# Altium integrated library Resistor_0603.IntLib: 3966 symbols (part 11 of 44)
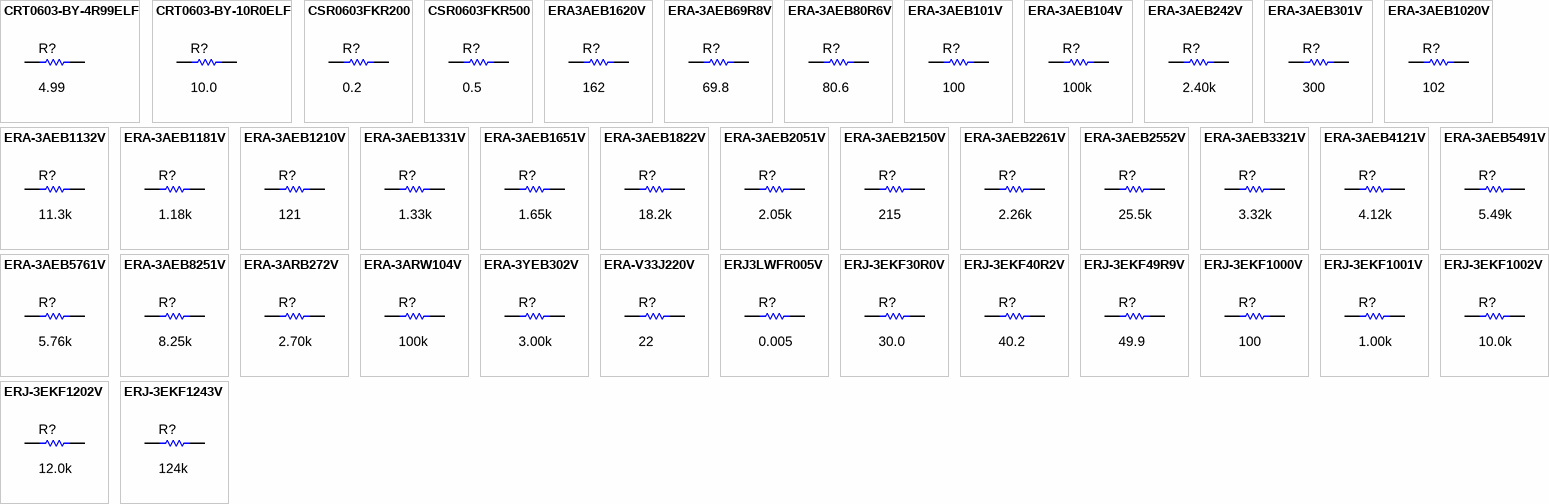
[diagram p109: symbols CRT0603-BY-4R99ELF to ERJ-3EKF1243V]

## ERA-3AEB2150V
designator R?  ValueDisplayed: 215  (hidden comment: ERA-3AEB2150V)
RES, 215, 0.1%, 0.1 W, AEC-Q200 Grade 0, 0603; Manufacturer: Panasonic; CompType: Resistor; Value: 215; Value_Code: 215R; Tolerance_%: 0.1; Value2: 0.1W; VDC_V: 75; TempCo: 25 ppm/C; SizeArea_mm2: 1.28; SizeX_mm: 1.6; SizeY_mm: 0.8; SizeZ_mm: 1; EIA_Code: E192; U/M: EA; AEC Category: Q200; AEC Qualified: Y; AEC Grade: 0
signal-integrity model Resistor
simulation model Resistor
footprint 0603
footprint 0603M
footprint 0603L
footprint 0603_HV
footprint 0603S
pins: 1, 2

## ERA-3AEB2261V
designator R?  ValueDisplayed: 2.26k  (hidden comment: ERA-3AEB2261V)
RES, 2.26 k, 0.1%, 0.1 W, AEC-Q200 Grade 0, 0603; Manufacturer: Panasonic; CompType: Resistor; Value: 2.26k; Res_ohm: 2260; Value_Code: 2k26; Tolerance_%: 0.1; Value2: 0.1W; VDC_V: 75; TempCo: 25 ppm/C; SizeArea_mm2: 1.28; SizeX_mm: 1.6; SizeY_mm: 0.8; SizeZ_mm: 1; EIA_Code: E192; U/M: EA; AEC Category: Q200; AEC Qualified: Y; AEC Grade: 0
signal-integrity model Resistor
simulation model Resistor
footprint 0603
footprint 0603M
footprint 0603L
footprint 0603_HV
footprint 0603S
pins: 1, 2

## ERA-3AEB2552V
designator R?  ValueDisplayed: 25.5k  (hidden comment: ERA-3AEB2552V)
RES, 25.5 k, 0.1%, 0.1 W, AEC-Q200 Grade 0, 0603; Manufacturer: Panasonic; CompType: Resistor; Value: 25.5k; Res_ohm: 25500; Value_Code: 25k5; Tolerance_%: 0.1; Value2: 0.1W; VDC_V: 75; TempCo: 25 ppm/C; SizeArea_mm2: 1.28; SizeX_mm: 1.6; SizeY_mm: 0.8; SizeZ_mm: 1; EIA_Code: E192; U/M: EA; AEC Category: Q200; AEC Qualified: Y; AEC Grade: 0; Green_Lifecycle: Not Set; Green_REACh: Incomplete
signal-integrity model Resistor
simulation model Resistor
footprint 0603
footprint 0603M
footprint 0603L
footprint 0603_HV
footprint 0603S
pins: 1, 2

## ERA-3AEB3321V
designator R?  ValueDisplayed: 3.32k  (hidden comment: ERA-3AEB3321V)
RES, 3.32 k, 0.1%, 0.1 W, AEC-Q200 Grade 0, 0603; Manufacturer: Panasonic; CompType: Resistor; Value: 3.32k; Res_ohm: 3320; Value_Code: 3k32; Tolerance_%: 0.1; Value2: 0.1W; VDC_V: 75; TempCo: 25 ppm/C; SizeArea_mm2: 1.28; SizeX_mm: 1.6; SizeY_mm: 0.8; SizeZ_mm: 1; EIA_Code: E192; U/M: EA; AEC Category: Q200; AEC Qualified: Y; AEC Grade: 0
signal-integrity model Resistor
simulation model Resistor
footprint 0603
footprint 0603M
footprint 0603L
footprint 0603_HV
footprint 0603S
pins: 1, 2

## ERA-3AEB4121V
designator R?  ValueDisplayed: 4.12k  (hidden comment: ERA-3AEB4121V)
RES, 4.12 k, 0.1%, 0.1 W, AEC-Q200 Grade 0, 0603; Manufacturer: Panasonic; CompType: Resistor; Value: 4.12k; Res_ohm: 4120; Value_Code: 4k12; Tolerance_%: 0.1; Value2: 0.1W; VDC_V: 75; TempCo: 25 ppm/C; SizeArea_mm2: 1.28; SizeX_mm: 1.6; SizeY_mm: 0.8; SizeZ_mm: 1; EIA_Code: E192; U/M: EA; AEC Category: Q200; AEC Qualified: Y; AEC Grade: 0
signal-integrity model Resistor
simulation model Resistor
footprint 0603
footprint 0603M
footprint 0603L
footprint 0603_HV
footprint 0603S
pins: 1, 2

## ERA-3AEB5491V
designator R?  ValueDisplayed: 5.49k  (hidden comment: ERA-3AEB5491V)
RES, 5.49 k, 0.1%, 0.1 W, AEC-Q200 Grade 0, 0603; Manufacturer: Panasonic; CompType: Resistor; Value: 5.49k; Res_ohm: 5490; Value_Code: 5k49; Tolerance_%: 0.1; Value2: 0.1W; VDC_V: 75; TempCo: 25 ppm/C; SizeArea_mm2: 1.28; SizeX_mm: 1.6; SizeY_mm: 0.8; SizeZ_mm: 1; EIA_Code: E192; U/M: EA; AEC Category: Q200; AEC Qualified: Y; AEC Grade: 0
signal-integrity model Resistor
simulation model Resistor
footprint 0603
footprint 0603M
footprint 0603L
footprint 0603_HV
footprint 0603S
pins: 1, 2

## ERA-3AEB5761V
designator R?  ValueDisplayed: 5.76k  (hidden comment: ERA-3AEB5761V)
RES, 5.76 k, 0.1%, 0.1 W, AEC-Q200 Grade 0, 0603; Manufacturer: Panasonic; CompType: Resistor; Value: 5.76k; Res_ohm: 5760; Value_Code: 5k76; Tolerance_%: 0.1; Value2: 0.1W; VDC_V: 75; TempCo: 25 ppm/C; SizeArea_mm2: 1.28; SizeX_mm: 1.6; SizeY_mm: 0.8; SizeZ_mm: 1; EIA_Code: E192; U/M: EA; AEC Category: Q200; AEC Qualified: Y; AEC Grade: 0
signal-integrity model Resistor
simulation model Resistor
footprint 0603
footprint 0603M
footprint 0603L
footprint 0603_HV
footprint 0603S
pins: 1, 2

## ERA-3AEB8251V
designator R?  ValueDisplayed: 8.25k  (hidden comment: ERA-3AEB8251V)
RES, 8.25 k, 0.1%, 0.1 W, AEC-Q200 Grade 0, 0603; Manufacturer: Panasonic; CompType: Resistor; Value: 8.25k; Res_ohm: 8250; Value_Code: 8k25; Tolerance_%: 0.1; Value2: 0.1W; VDC_V: 75; TempCo: 25 ppm/C; SizeArea_mm2: 1.28; SizeX_mm: 1.6; SizeY_mm: 0.8; SizeZ_mm: 1; EIA_Code: E192; U/M: EA; AEC Category: Q200; AEC Qualified: Y; AEC Grade: 0
signal-integrity model Resistor
simulation model Resistor
footprint 0603
footprint 0603M
footprint 0603L
footprint 0603_HV
footprint 0603S
pins: 1, 2

## ERA-3ARB272V
designator R?  ValueDisplayed: 2.70k  (hidden comment: ERA-3ARB272V)
RES, 2.70 k, 0.1%, 0.1 W, 0603; Manufacturer: Panasonic; CompType: Resistor; Value: 2.70k; Res_ohm: 2700; Value_Code: 2k70; Tolerance_%: 0.1; Value2: 0.1W; VDC_V: 75; TempCo: 10 ppm/C; SizeArea_mm2: 1.28; SizeX_mm: 1.6; SizeY_mm: 0.8; SizeZ_mm: 1; U/M: EA; AEC Category: Q200
signal-integrity model Resistor
simulation model Resistor
footprint 0603
footprint 0603M
footprint 0603L
footprint 0603_HV
footprint 0603S
pins: 1, 2

## ERA-3ARW104V
designator R?  ValueDisplayed: 100k  (hidden comment: ERA-3ARW104V)
RES, 100 k, 0.05%, 0.1 W, AEC-Q200 Grade 0, 0603; Manufacturer: Panasonic; CompType: Resistor; Value: 100k; Res_ohm: 100000; Tolerance_%: 0.05; Power_W: 0.1; Value2: 0.1W; VDC_V: 75; TempCo: 10 ppm/C; SizeArea_mm2: 1.28; SizeX_mm: 1.6; SizeY_mm: 0.8; SizeZ_mm: 1; U/M: EA; AEC Category: Q200; AEC Qualified: Y; AEC Grade: 0
signal-integrity model Resistor
simulation model Resistor
footprint 0603
footprint 0603M
footprint 0603L
footprint 0603_HV
footprint 0603S
pins: 1, 2

## ERA-3YEB302V
designator R?  ValueDisplayed: 3.00k  (hidden comment: ERA-3YEB302V)
RES, 3.00 k, 0.1%, 0.1 W, 0603; Manufacturer: Panasonic; CompType: Resistor; Value: 3.00k; Res_ohm: 3000; Value_Code: 3k00; Tolerance_%: 0.1; Value2: 0.1W; VDC_V: 75; TempCo: 25 ppm/C; SizeArea_mm2: 1.28; SizeX_mm: 1.6; SizeY_mm: 0.8; SizeZ_mm: 1; U/M: EA; AEC Category: Q200
signal-integrity model Resistor
simulation model Resistor
footprint 0603
footprint 0603M
footprint 0603L
footprint 0603_HV
footprint 0603S
pins: 1, 2

## ERA-V33J220V
designator R?  ValueDisplayed: 22  (hidden comment: ERA-V33J220V)
RES, 22, 5%, 0.063 W, 0603; Manufacturer: Panasonic; CompType: Resistor; Value: 22; Value_Code: 22R0; Tolerance_%: 5; Power_W: 0.063; Value2: 0.063W; TempCo: 3300 ppm/C; SizeArea_mm2: 1.28; SizeX_mm: 1.6; SizeY_mm: 0.8; SizeZ_mm: 1; EIA_Code: E24; U/M: EA; AEC Category: Q200; AEC Qualified: N; Green_Lifecycle: Not Set; Green_REACh: Incomplete
signal-integrity model Resistor
simulation model Resistor
footprint 0603
footprint 0603M
footprint 0603L
footprint 0603_HV
footprint 0603S
pins: 1, 2

## ERJ3LWFR005V
designator R?  ValueDisplayed: 0.005  (hidden comment: ERJ3LWFR005V)
RES, 0.005, 1%, 0.25 W, AEC-Q200 Grade 1, 0603; Manufacturer: Panasonic; CompType: Resistor; Value: 0.005; Value_Code: 5L000; Tolerance_%: 1; Power_W: 0.25; Value2: 0.25W; TempCo: ppm/C; SizeArea_mm2: 1.28; SizeX_mm: 1.6; SizeY_mm: 0.8; EIA_Code: E96; U/M: EA; AEC Category: Q200; AEC Qualified: Y; Green_Lifecycle: Not Set; Green_REACh: Incomplete
signal-integrity model Resistor
simulation model Resistor
footprint 0603
footprint 0603M
footprint 0603L
footprint 0603_HV
footprint 0603S
pins: 1, 2

## ERJ-3EKF30R0V
designator R?  ValueDisplayed: 30.0  (hidden comment: ERJ-3EKF30R0V)
RES, 30.0, 1%, 0.1 W, AEC-Q200 Grade 0, 0603; Manufacturer: Panasonic; CompType: Resistor; Value: 30.0; Res_ohm: 30; Value_Code: 30R0; Tolerance_%: 1; Power_W: 0.1; Value2: 0.1W; TempCo: 100 ppm/C; SizeArea_mm2: 1.28; SizeX_mm: 1.6; SizeY_mm: 0.8; U/M: EA; AEC Category: Q200; AEC Qualified: Y; AEC Grade: 0
signal-integrity model Resistor
simulation model Resistor
footprint 0603
footprint 0603M
footprint 0603L
footprint 0603_HV
footprint 0603S
pins: 1, 2

## ERJ-3EKF40R2V
designator R?  ValueDisplayed: 40.2  (hidden comment: ERJ-3EKF40R2V)
RES, 40.2, 1%, 0.1 W, AEC-Q200 Grade 0, 0603; Manufacturer: Panasonic; CompType: Resistor; Value: 40.2; Value_Code: 40R2; Tolerance_%: 1; Power_W: 0.1; Value2: 0.1W; TempCo: 100 ppm/C; SizeArea_mm2: 1.28; SizeX_mm: 1.6; SizeY_mm: 0.8; EIA_Code: E96; U/M: EA; AEC Category: Q200; AEC Qualified: Y; AEC Grade: 0; Green_Lifecycle: Active; Green_REACh: Passed
signal-integrity model Resistor
simulation model Resistor
footprint 0603
footprint 0603M
footprint 0603L
footprint 0603_HV
footprint 0603S
pins: 1, 2

## ERJ-3EKF49R9V
designator R?  ValueDisplayed: 49.9  (hidden comment: ERJ-3EKF49R9V)
RES, 49.9, 1%, 0.1 W, AEC-Q200 Grade 0, 0603; Manufacturer: Panasonic; CompType: Resistor; Value: 49.9; Value_Code: 49R9; Tolerance_%: 1; Power_W: 0.1; Value2: 0.1W; TempCo: 100 ppm/C; SizeArea_mm2: 1.28; SizeX_mm: 1.6; SizeY_mm: 0.8; EIA_Code: E96; U/M: EA; AEC Category: Q200; AEC Qualified: Y; AEC Grade: 0; Green_Lifecycle: Active; Green_REACh: Passed
signal-integrity model Resistor
simulation model Resistor
footprint 0603
footprint 0603M
footprint 0603L
footprint 0603_HV
footprint 0603S
pins: 1, 2

## ERJ-3EKF1000V
designator R?  ValueDisplayed: 100  (hidden comment: ERJ-3EKF1000V)
RES, 100, 1%, 0.1 W, AEC-Q200 Grade 0, 0603; Manufacturer: Panasonic; CompType: Resistor; Value: 100; Value_Code: 100R; Tolerance_%: 1; Power_W: 0.1; Value2: 0.1W; TempCo: 100 ppm/C; SizeArea_mm2: 1.28; SizeX_mm: 1.6; SizeY_mm: 0.8; EIA_Code: E96; U/M: EA; AEC Category: Q200; AEC Qualified: Y; AEC Grade: 0; Green_Lifecycle: Active; Green_REACh: Passed
signal-integrity model Resistor
simulation model Resistor
footprint 0603
footprint 0603M
footprint 0603L
footprint 0603_HV
footprint 0603S
pins: 1, 2

## ERJ-3EKF1001V
designator R?  ValueDisplayed: 1.00k  (hidden comment: ERJ-3EKF1001V)
RES, 1.00 k, 1%, 0.1 W, AEC-Q200 Grade 0, 0603; Manufacturer: Panasonic; CompType: Resistor; Value: 1.00k; Res_ohm: 1000; Value_Code: 1k00; Tolerance_%: 1; Power_W: 0.1; Value2: 0.1W; VDC_V: 75; TempCo: 100 ppm/C; SizeArea_mm2: 1.28; SizeX_mm: 1.6; SizeY_mm: 0.8; EIA_Code: E96; U/M: EA; AEC Category: Q200; AEC Qualified: Y; AEC Grade: 0; Green_Lifecycle: Active; Green_REACh: Passed
signal-integrity model Resistor
simulation model Resistor
footprint 0603
footprint 0603M
footprint 0603L
footprint 0603_HV
footprint 0603S
pins: 1, 2

## ERJ-3EKF1002V
designator R?  ValueDisplayed: 10.0k  (hidden comment: ERJ-3EKF1002V)
RES, 10.0 k, 1%, 0.1 W, 0603; Manufacturer: Panasonic; CompType: Resistor; Value: 10.0k; Res_ohm: 10000; Value_Code: 10k0; Tolerance_%: 1; Power_W: 0.1; Value2: 0.1W; VDC_V: 75; TempCo: 100 ppm/C; SizeArea_mm2: 1.28; SizeX_mm: 1.6; SizeY_mm: 0.8; EIA_Code: E96; U/M: EA; AEC Category: Q200; Green_Lifecycle: Active; Green_REACh: Passed
signal-integrity model Resistor
simulation model Resistor
footprint 0603
footprint 0603M
footprint 0603L
footprint 0603_HV
footprint 0603S
pins: 1, 2

## ERJ-3EKF1202V
designator R?  ValueDisplayed: 12.0k  (hidden comment: ERJ-3EKF1202V)
RES, 12.0 k, 1%, 0.1 W, 0603; Manufacturer: Panasonic; CompType: Resistor; Value: 12.0k; Res_ohm: 12000; Value_Code: 12k0; Tolerance_%: 1; Power_W: 0.1; Value2: 0.1W; VDC_V: 75; TempCo: 100 ppm/C; SizeArea_mm2: 1.28; SizeX_mm: 1.6; SizeY_mm: 0.8; U/M: EA; AEC Category: Q200; Green_Lifecycle: Active; Green_REACh: Passed
signal-integrity model Resistor
simulation model Resistor
footprint 0603
footprint 0603M
footprint 0603L
footprint 0603_HV
footprint 0603S
pins: 1, 2

## ERJ-3EKF1243V
designator R?  ValueDisplayed: 124k  (hidden comment: ERJ-3EKF1243V)
RES, 124 k, 1%, 0.1 W, AEC-Q200 Grade 0, 0603; Manufacturer: Panasonic; CompType: Resistor; Value: 124k; Res_ohm: 124000; Tolerance_%: 1; Power_W: 0.1; Value2: 0.1W; VDC_V: 75; TempCo: 100 ppm/C; SizeArea_mm2: 1.28; SizeX_mm: 1.6; SizeY_mm: 0.8; EIA_Code: E96; U/M: EA; AEC Category: Q200; AEC Qualified: Y; AEC Grade: 0
signal-integrity model Resistor
simulation model Resistor
footprint 0603
footprint 0603M
footprint 0603L
footprint 0603_HV
footprint 0603S
pins: 1, 2

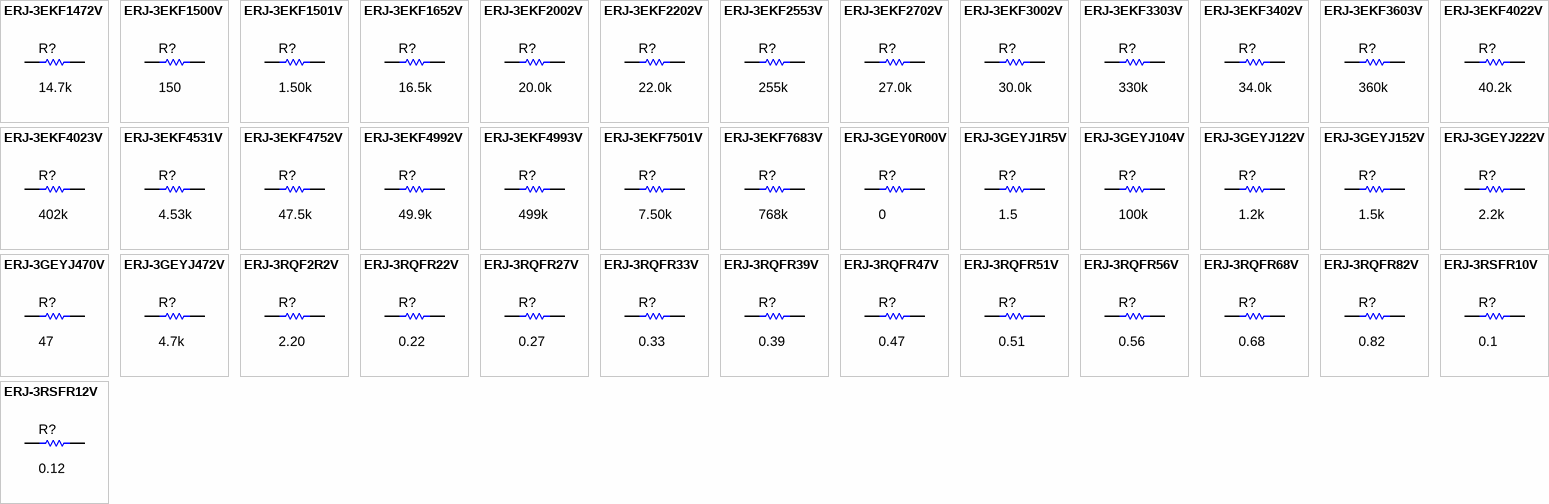
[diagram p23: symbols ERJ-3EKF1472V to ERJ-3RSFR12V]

## ERJ-3EKF1472V
designator R?  ValueDisplayed: 14.7k  (hidden comment: ERJ-3EKF1472V)
RES, 14.7 k, 1%, 0.1 W, AEC-Q200 Grade 0, 0603; Manufacturer: Panasonic; CompType: Resistor; Value: 14.7k; Res_ohm: 14700; Value_Code: 14k7; Tolerance_%: 1; Power_W: 0.1; Value2: 0.1W; VDC_V: 50; TempCo: 100 ppm/C; SizeArea_mm2: 1.28; SizeX_mm: 1.6; SizeY_mm: 0.8; EIA_Code: E96; U/M: EA; AEC Category: Q200; AEC Qualified: Y; AEC Grade: 0; Green_Lifecycle: Active; Green_REACh: Passed
signal-integrity model Resistor
simulation model Resistor
footprint 0603
footprint 0603M
footprint 0603L
footprint 0603_HV
footprint 0603S
pins: 1, 2

## ERJ-3EKF1500V
designator R?  ValueDisplayed: 150  (hidden comment: ERJ-3EKF1500V)
RES, 150, 1%, 0.1 W, AEC-Q200 Grade 0, 0603; Manufacturer: Panasonic; CompType: Resistor; Value: 150; Value_Code: 150R; Tolerance_%: 1; Power_W: 0.1; Value2: 0.1W; VDC_V: 50; TempCo: 100 ppm/C; SizeArea_mm2: 1.28; SizeX_mm: 1.6; SizeY_mm: 0.8; EIA_Code: E96; U/M: EA; AEC Category: Q200; AEC Qualified: Y; AEC Grade: 0; Green_Lifecycle: Active; Green_REACh: Passed
signal-integrity model Resistor
simulation model Resistor
footprint 0603
footprint 0603M
footprint 0603L
footprint 0603_HV
footprint 0603S
pins: 1, 2

## ERJ-3EKF1501V
designator R?  ValueDisplayed: 1.50k  (hidden comment: ERJ-3EKF1501V)
RES, 1.50 k, 1%, 0.1 W, 0603; Manufacturer: Panasonic; CompType: Resistor; Value: 1.50k; Res_ohm: 1500; Value_Code: 1k50; Tolerance_%: 1; Power_W: 0.1; Value2: 0.1W; VDC_V: 75; TempCo: 100 ppm/C; SizeArea_mm2: 1.28; SizeX_mm: 1.6; SizeY_mm: 0.8; EIA_Code: E96; U/M: EA; AEC Category: Q200; Green_Lifecycle: Active; Green_REACh: Passed
signal-integrity model Resistor
simulation model Resistor
footprint 0603
footprint 0603M
footprint 0603L
footprint 0603_HV
footprint 0603S
pins: 1, 2

## ERJ-3EKF1652V
designator R?  ValueDisplayed: 16.5k  (hidden comment: ERJ-3EKF1652V)
RES, 16.5 k, 1%, 0.1 W, AEC-Q200 Grade 0, 0603; Manufacturer: Panasonic; CompType: Resistor; Value: 16.5k; Res_ohm: 16500; Value_Code: 16k5; Tolerance_%: 1; Power_W: 0.1; Value2: 0.1W; VDC_V: 75; TempCo: 100 ppm/C; SizeArea_mm2: 1.28; SizeX_mm: 1.6; SizeY_mm: 0.8; EIA_Code: E96; U/M: EA; AEC Category: Q200; AEC Qualified: Y; AEC Grade: 0; Green_Lifecycle: Active; Green_REACh: Passed
signal-integrity model Resistor
simulation model Resistor
footprint 0603
footprint 0603M
footprint 0603L
footprint 0603_HV
footprint 0603S
pins: 1, 2

## ERJ-3EKF2002V
designator R?  ValueDisplayed: 20.0k  (hidden comment: ERJ-3EKF2002V)
RES, 20.0 k, 1%, 0.1 W, AEC-Q200 Grade 0, 0603; Manufacturer: Panasonic; CompType: Resistor; Value: 20.0k; Res_ohm: 20000; Value_Code: 20k0; Tolerance_%: 1; Power_W: 0.1; Value2: 0.1W; VDC_V: 75; TempCo: 100 ppm/C; SizeArea_mm2: 1.28; SizeX_mm: 1.6; SizeY_mm: 0.8; EIA_Code: E96; U/M: EA; AEC Category: Q200; AEC Qualified: Y; AEC Grade: 0; Green_Lifecycle: Active; Green_REACh: Passed
signal-integrity model Resistor
simulation model Resistor
footprint 0603
footprint 0603M
footprint 0603L
footprint 0603_HV
footprint 0603S
pins: 1, 2

## ERJ-3EKF2202V
designator R?  ValueDisplayed: 22.0k  (hidden comment: ERJ-3EKF2202V)
RES, 22.0 k, 1%, 0.1 W, AEC-Q200 Grade 0, 0603; Manufacturer: Panasonic; CompType: Resistor; Value: 22.0k; Res_ohm: 22000; Value_Code: 22k0; Tolerance_%: 1; Power_W: 0.1; Value2: 0.1W; VDC_V: 50; TempCo: 100 ppm/C; SizeArea_mm2: 1.28; SizeX_mm: 1.6; SizeY_mm: 0.8; U/M: EA; AEC Category: Q200; AEC Qualified: Y; AEC Grade: 0; Green_Lifecycle: Active; Green_REACh: Passed
signal-integrity model Resistor
simulation model Resistor
footprint 0603
footprint 0603M
footprint 0603L
footprint 0603_HV
footprint 0603S
pins: 1, 2

## ERJ-3EKF2553V
designator R?  ValueDisplayed: 255k  (hidden comment: ERJ-3EKF2553V)
RES, 255 k, 1%, 0.1 W, AEC-Q200 Grade 0, 0603; Manufacturer: Panasonic; CompType: Resistor; Value: 255k; Res_ohm: 255000; Tolerance_%: 1; Power_W: 0.1; Value2: 0.1W; VDC_V: 75; TempCo: 100 ppm/C; SizeArea_mm2: 1.28; SizeX_mm: 1.6; SizeY_mm: 0.8; EIA_Code: E96; U/M: EA; AEC Category: Q200; AEC Qualified: Y; AEC Grade: 0
signal-integrity model Resistor
simulation model Resistor
footprint 0603
footprint 0603M
footprint 0603L
footprint 0603_HV
footprint 0603S
pins: 1, 2

## ERJ-3EKF2702V
designator R?  ValueDisplayed: 27.0k  (hidden comment: ERJ-3EKF2702V)
RES, 27.0 k, 1%, 0.1 W, AEC-Q200 Grade 0, 0603; Manufacturer: Panasonic; CompType: Resistor; Value: 27.0k; Res_ohm: 27000; Value_Code: 27k0; Tolerance_%: 1; Power_W: 0.1; Value2: 0.1W; VDC_V: 50; TempCo: 100 ppm/C; SizeArea_mm2: 1.28; SizeX_mm: 1.6; SizeY_mm: 0.8; U/M: EA; AEC Category: Q200; AEC Qualified: Y; AEC Grade: 0
signal-integrity model Resistor
simulation model Resistor
footprint 0603
footprint 0603M
footprint 0603L
footprint 0603_HV
footprint 0603S
pins: 1, 2

## ERJ-3EKF3002V
designator R?  ValueDisplayed: 30.0k  (hidden comment: ERJ-3EKF3002V)
RES, 30.0 k, 1%, 0.1 W, AEC-Q200 Grade 0, 0603; Manufacturer: Panasonic; CompType: Resistor; Value: 30.0k; Res_ohm: 30000; Value_Code: 30k0; Tolerance_%: 1; Power_W: 0.1; Value2: 0.1W; VDC_V: 75; TempCo: 100 ppm/C; SizeArea_mm2: 1.28; SizeX_mm: 1.6; SizeY_mm: 0.8; U/M: EA; AEC Category: Q200; AEC Qualified: Y; AEC Grade: 0
signal-integrity model Resistor
simulation model Resistor
footprint 0603
footprint 0603M
footprint 0603L
footprint 0603_HV
footprint 0603S
pins: 1, 2

## ERJ-3EKF3303V
designator R?  ValueDisplayed: 330k  (hidden comment: ERJ-3EKF3303V)
RES, 330 k, 1%, 0.1 W, AEC-Q200 Grade 0, 0603; Manufacturer: Panasonic; CompType: Resistor; Value: 330k; Res_ohm: 330000; Tolerance_%: 1; Power_W: 0.1; Value2: 0.1W; VDC_V: 75; TempCo: 100 ppm/C; SizeArea_mm2: 1.28; SizeX_mm: 1.6; SizeY_mm: 0.8; U/M: EA; AEC Category: Q200; AEC Qualified: Y; AEC Grade: 0; Green_Lifecycle: Active; Green_REACh: Passed
signal-integrity model Resistor
simulation model Resistor
footprint 0603
footprint 0603M
footprint 0603L
footprint 0603_HV
footprint 0603S
pins: 1, 2

## ERJ-3EKF3402V
designator R?  ValueDisplayed: 34.0k  (hidden comment: ERJ-3EKF3402V)
RES, 34.0 k, 1%, 0.1 W, AEC-Q200 Grade 0, 0603; Manufacturer: Panasonic; CompType: Resistor; Value: 34.0k; Res_ohm: 34000; Value_Code: 34k0; Tolerance_%: 1; Power_W: 0.1; Value2: 0.1W; VDC_V: 75; TempCo: 100 ppm/C; SizeArea_mm2: 1.28; SizeX_mm: 1.6; SizeY_mm: 0.8; EIA_Code: E96; U/M: EA; AEC Category: Q200; AEC Qualified: Y; AEC Grade: 0
signal-integrity model Resistor
simulation model Resistor
footprint 0603
footprint 0603M
footprint 0603L
footprint 0603_HV
footprint 0603S
pins: 1, 2

## ERJ-3EKF3603V
designator R?  ValueDisplayed: 360k  (hidden comment: ERJ-3EKF3603V)
RES, 360 k, 1%, 0.1 W, AEC-Q200 Grade 0, 0603; Manufacturer: Panasonic; CompType: Resistor; Value: 360k; Res_ohm: 360000; Tolerance_%: 1; Power_W: 0.1; Value2: 0.1W; VDC_V: 75; TempCo: 100 ppm/C; SizeArea_mm2: 1.28; SizeX_mm: 1.6; SizeY_mm: 0.8; U/M: EA; AEC Category: Q200; AEC Qualified: Y; AEC Grade: 0; Green_Lifecycle: Active; Green_REACh: Passed
signal-integrity model Resistor
simulation model Resistor
footprint 0603
footprint 0603M
footprint 0603L
footprint 0603_HV
footprint 0603S
pins: 1, 2

## ERJ-3EKF4022V
designator R?  ValueDisplayed: 40.2k  (hidden comment: ERJ-3EKF4022V)
RES, 40.2 k, 1%, 0.1 W, AEC-Q200 Grade 0, 0603; Manufacturer: Panasonic; CompType: Resistor; Value: 40.2k; Res_ohm: 40200; Value_Code: 40k2; Tolerance_%: 1; Power_W: 0.1; Value2: 0.1W; VDC_V: 75; TempCo: 100 ppm/C; SizeArea_mm2: 1.28; SizeX_mm: 1.6; SizeY_mm: 0.8; EIA_Code: E96; U/M: EA; AEC Category: Q200; AEC Qualified: Y; AEC Grade: 0; Green_Lifecycle: Active; Green_REACh: Passed
signal-integrity model Resistor
simulation model Resistor
footprint 0603
footprint 0603M
footprint 0603L
footprint 0603_HV
footprint 0603S
pins: 1, 2

## ERJ-3EKF4023V
designator R?  ValueDisplayed: 402k  (hidden comment: ERJ-3EKF4023V)
RES, 402 k, 1%, 0.1 W, AEC-Q200 Grade 0, 0603; Manufacturer: Panasonic; CompType: Resistor; Value: 402k; Res_ohm: 402000; Tolerance_%: 1; Power_W: 0.1; Value2: 0.1W; VDC_V: 50; TempCo: 100 ppm/C; SizeArea_mm2: 1.28; SizeX_mm: 1.6; SizeY_mm: 0.8; EIA_Code: E96; U/M: EA; AEC Category: Q200; AEC Qualified: Y; AEC Grade: 0; Green_Lifecycle: Active; Green_REACh: Passed
signal-integrity model Resistor
simulation model Resistor
footprint 0603
footprint 0603M
footprint 0603L
footprint 0603_HV
footprint 0603S
pins: 1, 2

## ERJ-3EKF4531V
designator R?  ValueDisplayed: 4.53k  (hidden comment: ERJ-3EKF4531V)
RES, 4.53 k, 1%, 0.1 W, AEC-Q200 Grade 0, 0603; Manufacturer: Panasonic; CompType: Resistor; Value: 4.53k; Res_ohm: 4530; Value_Code: 4k53; Tolerance_%: 1; Power_W: 0.1; Value2: 0.1W; VDC_V: 75; TempCo: 100 ppm/C; SizeArea_mm2: 1.28; SizeX_mm: 1.6; SizeY_mm: 0.8; EIA_Code: E96; U/M: EA; AEC Category: Q200; AEC Qualified: Y; AEC Grade: 0
signal-integrity model Resistor
simulation model Resistor
footprint 0603
footprint 0603M
footprint 0603L
footprint 0603_HV
footprint 0603S
pins: 1, 2

## ERJ-3EKF4752V
designator R?  ValueDisplayed: 47.5k  (hidden comment: ERJ-3EKF4752V)
RES, 47.5 k, 1%, 0.1 W, AEC-Q200 Grade 0, 0603; Manufacturer: Panasonic; CompType: Resistor; Value: 47.5k; Res_ohm: 47500; Value_Code: 47k5; Tolerance_%: 1; Power_W: 0.1; Value2: 0.1W; VDC_V: 50; TempCo: 100 ppm/C; SizeArea_mm2: 1.28; SizeX_mm: 1.6; SizeY_mm: 0.8; EIA_Code: E96; U/M: EA; AEC Category: Q200; AEC Qualified: Y; AEC Grade: 0; Green_Lifecycle: Active; Green_REACh: Passed
signal-integrity model Resistor
simulation model Resistor
footprint 0603
footprint 0603M
footprint 0603L
footprint 0603_HV
footprint 0603S
pins: 1, 2

## ERJ-3EKF4992V
designator R?  ValueDisplayed: 49.9k  (hidden comment: ERJ-3EKF4992V)
RES, 49.9 k, 1%, 0.1 W, AEC-Q200 Grade 0, 0603; Manufacturer: Panasonic; CompType: Resistor; Value: 49.9k; Res_ohm: 49900; Value_Code: 49k9; Tolerance_%: 1; Power_W: 0.1; Value2: 0.1W; VDC_V: 75; TempCo: 100 ppm/C; SizeArea_mm2: 1.28; SizeX_mm: 1.6; SizeY_mm: 0.8; EIA_Code: E96; U/M: EA; AEC Category: Q200; AEC Qualified: Y; AEC Grade: 0; Green_Lifecycle: Active; Green_REACh: Passed
signal-integrity model Resistor
simulation model Resistor
footprint 0603
footprint 0603M
footprint 0603L
footprint 0603_HV
footprint 0603S
pins: 1, 2

## ERJ-3EKF4993V
designator R?  ValueDisplayed: 499k  (hidden comment: ERJ-3EKF4993V)
RES, 499 k, 1%, 0.1 W, AEC-Q200 Grade 0, 0603; Manufacturer: Panasonic; CompType: Resistor; Value: 499k; Res_ohm: 499000; Tolerance_%: 1; Power_W: 0.1; Value2: 0.1W; VDC_V: 75; TempCo: 100 ppm/C; SizeArea_mm2: 1.28; SizeX_mm: 1.6; SizeY_mm: 0.8; EIA_Code: E96; U/M: EA; AEC Category: Q200; AEC Qualified: Y; AEC Grade: 0; Green_Lifecycle: Active; Green_REACh: Passed
signal-integrity model Resistor
simulation model Resistor
footprint 0603
footprint 0603M
footprint 0603L
footprint 0603_HV
footprint 0603S
pins: 1, 2

## ERJ-3EKF7501V
designator R?  ValueDisplayed: 7.50k  (hidden comment: ERJ-3EKF7501V)
RES, 7.50 k, 1%, 0.1 W, 0603; Manufacturer: Panasonic; CompType: Resistor; Value: 7.50k; Res_ohm: 7500; Value_Code: 7k50; Tolerance_%: 1; Power_W: 0.1; Value2: 0.1W; VDC_V: 75; TempCo: 100 ppm/C; SizeArea_mm2: 1.28; SizeX_mm: 1.6; SizeY_mm: 0.8; EIA_Code: E96; U/M: EA; AEC Category: Q200; Green_Lifecycle: Active; Green_REACh: Passed
signal-integrity model Resistor
simulation model Resistor
footprint 0603
footprint 0603M
footprint 0603L
footprint 0603_HV
footprint 0603S
pins: 1, 2

## ERJ-3EKF7683V
designator R?  ValueDisplayed: 768k  (hidden comment: ERJ-3EKF7683V)
RES, 768 k, 1%, 0.1 W, 0603; Manufacturer: Panasonic; CompType: Resistor; Value: 768k; Res_ohm: 768000; Tolerance_%: 1; Power_W: 0.1; Value2: 0.1W; VDC_V: 75; TempCo: 100 ppm/C; SizeArea_mm2: 1.28; SizeX_mm: 1.6; SizeY_mm: 0.8; EIA_Code: E96; U/M: EA; AEC Category: Q200
signal-integrity model Resistor
simulation model Resistor
footprint 0603
footprint 0603M
footprint 0603L
footprint 0603_HV
footprint 0603S
pins: 1, 2

## ERJ-3GEY0R00V
designator R?  ValueDisplayed: 0  (hidden comment: ERJ-3GEY0R00V)
RES, 0, 5%, 0.1 W, 0603; Manufacturer: Panasonic; CompType: Resistor; Value: 0; Value_Code: 0000; Tolerance_%: 5; Power_W: 0.1; Value2: 0.1W; VDC_V: 50; TempCo: 600 ppm/C; SizeArea_mm2: 1.28; SizeX_mm: 1.6; SizeY_mm: 0.8; SizeZ_mm: 1; EIA_Code: E24; U/M: EA; AEC Category: Q200; Green_Lifecycle: Active; Green_REACh: Passed
signal-integrity model Resistor
simulation model Resistor
footprint 0603
footprint 0603M
footprint 0603L
footprint 0603_HV
footprint 0603S
pins: 1, 2

## ERJ-3GEYJ1R5V
designator R?  ValueDisplayed: 1.5  (hidden comment: ERJ-3GEYJ1R5V)
RES, 1.5, 5%, 0.1 W, 0603; Manufacturer: Panasonic; CompType: Resistor; Value: 1.5; Value_Code: 1R50; Tolerance_%: 5; Power_W: 0.1; Value2: 0.1W; VDC_V: 75; TempCo: 600 ppm/C; SizeArea_mm2: 1.28; SizeX_mm: 1.6; SizeY_mm: 0.8; SizeZ_mm: 1; EIA_Code: E24; U/M: EA; AEC Category: Q200
signal-integrity model Resistor
simulation model Resistor
footprint 0603
footprint 0603M
footprint 0603L
footprint 0603_HV
footprint 0603S
pins: 1, 2

## ERJ-3GEYJ104V
designator R?  ValueDisplayed: 100k  (hidden comment: ERJ-3GEYJ104V)
RES, 100 k, 5%, 0.1 W, AEC-Q200 Grade 0, 0603; Manufacturer: Panasonic; CompType: Resistor; Value: 100k; Res_ohm: 100000; Tolerance_%: 5; Power_W: 0.1; Value2: 0.1W; VDC_V: 50; TempCo: 200 ppm/C; SizeArea_mm2: 1.28; SizeX_mm: 1.6; SizeY_mm: 0.8; SizeZ_mm: 1; EIA_Code: E24; U/M: EA; AEC Category: Q200; AEC Qualified: Y; AEC Grade: 0; Green_Lifecycle: Active; Green_REACh: Passed
signal-integrity model Resistor
simulation model Resistor
footprint 0603
footprint 0603M
footprint 0603L
footprint 0603_HV
footprint 0603S
pins: 1, 2

## ERJ-3GEYJ122V
designator R?  ValueDisplayed: 1.2k  (hidden comment: ERJ-3GEYJ122V)
RES, 1.2 k, 5%, 0.1 W, AEC-Q200 Grade 0, 0603; Manufacturer: Panasonic; CompType: Resistor; Value: 1.2k; Res_ohm: 1200; Value_Code: 1k20; Tolerance_%: 5; Power_W: 0.1; Value2: 0.1W; VDC_V: 75; TempCo: 200 ppm/C; SizeArea_mm2: 1.28; SizeX_mm: 1.6; SizeY_mm: 0.8; SizeZ_mm: 1; EIA_Code: E24; U/M: EA; AEC Category: Q200; AEC Qualified: Y; AEC Grade: 0; Green_Lifecycle: Active; Green_REACh: Passed
signal-integrity model Resistor
simulation model Resistor
footprint 0603
footprint 0603M
footprint 0603L
footprint 0603_HV
footprint 0603S
pins: 1, 2

## ERJ-3GEYJ152V
designator R?  ValueDisplayed: 1.5k  (hidden comment: ERJ-3GEYJ152V)
RES, 1.5 k, 5%, 0.1 W, AEC-Q200 Grade 0, 0603; Manufacturer: Panasonic; CompType: Resistor; Value: 1.5k; Res_ohm: 1500; Value_Code: 1k50; Tolerance_%: 5; Power_W: 0.1; Value2: 0.1W; VDC_V: 75; TempCo: 200 ppm/C; SizeArea_mm2: 1.28; SizeX_mm: 1.6; SizeY_mm: 0.8; SizeZ_mm: 1; EIA_Code: E24; U/M: EA; AEC Category: Q200; AEC Qualified: Y; AEC Grade: 0; Green_Lifecycle: Active; Green_REACh: Passed
signal-integrity model Resistor
simulation model Resistor
footprint 0603
footprint 0603M
footprint 0603L
footprint 0603_HV
footprint 0603S
pins: 1, 2

## ERJ-3GEYJ222V
designator R?  ValueDisplayed: 2.2k  (hidden comment: ERJ-3GEYJ222V)
RES, 2.2 k, 5%, 0.1 W, AEC-Q200 Grade 0, 0603; Manufacturer: Panasonic; CompType: Resistor; Value: 2.2k; Res_ohm: 2200; Value_Code: 2k20; Tolerance_%: 5; Power_W: 0.1; Value2: 0.1W; VDC_V: 75; TempCo: 200 ppm/C; SizeArea_mm2: 1.28; SizeX_mm: 1.6; SizeY_mm: 0.8; SizeZ_mm: 1; EIA_Code: E24; U/M: EA; AEC Category: Q200; AEC Qualified: Y; AEC Grade: 0; Green_Lifecycle: Active; Green_REACh: Passed
signal-integrity model Resistor
simulation model Resistor
footprint 0603
footprint 0603M
footprint 0603L
footprint 0603_HV
footprint 0603S
pins: 1, 2

## ERJ-3GEYJ470V
designator R?  ValueDisplayed: 47  (hidden comment: ERJ-3GEYJ470V)
RES, 47, 5%, 0.1 W, AEC-Q200 Grade 0, 0603; Manufacturer: Panasonic; CompType: Resistor; Value: 47; Value_Code: 47R0; Tolerance_%: 5; Power_W: 0.1; Value2: 0.1W; TempCo: 200 ppm/C; SizeArea_mm2: 1.28; SizeX_mm: 1.6; SizeY_mm: 0.8; SizeZ_mm: 1; EIA_Code: E24; U/M: EA; AEC Category: Q200; AEC Qualified: Y; AEC Grade: 0; Green_Lifecycle: Active; Green_REACh: Passed
signal-integrity model Resistor
simulation model Resistor
footprint 0603
footprint 0603M
footprint 0603L
footprint 0603_HV
footprint 0603S
pins: 1, 2

## ERJ-3GEYJ472V
designator R?  ValueDisplayed: 4.7k  (hidden comment: ERJ-3GEYJ472V)
RES, 4.7 k, 5%, 0.1 W, AEC-Q200 Grade 0, 0603; Manufacturer: Panasonic; CompType: Resistor; Value: 4.7k; Res_ohm: 4700; Value_Code: 4k70; Tolerance_%: 5; Power_W: 0.1; Value2: 0.1W; VDC_V: 75; TempCo: 200 ppm/C; SizeArea_mm2: 1.28; SizeX_mm: 1.6; SizeY_mm: 0.8; SizeZ_mm: 1; EIA_Code: E24; U/M: EA; AEC Category: Q200; AEC Qualified: Y; AEC Grade: 0; Green_Lifecycle: Active; Green_REACh: Passed
signal-integrity model Resistor
simulation model Resistor
footprint 0603
footprint 0603M
footprint 0603L
footprint 0603_HV
footprint 0603S
pins: 1, 2

## ERJ-3RQF2R2V
designator R?  ValueDisplayed: 2.20  (hidden comment: ERJ-3RQF2R2V)
RES, 2.20, 1%, 0.1 W, 0603; Manufacturer: Panasonic; CompType: Resistor; Value: 2.20; Res_ohm: 2.2; Value_Code: 2R20; Tolerance_%: 1; Power_W: 0.1; Value2: 0.1W; TempCo: 200 ppm/C; SizeArea_mm2: 1.28; SizeX_mm: 1.6; SizeY_mm: 0.8; U/M: EA; AEC Category: Q200
signal-integrity model Resistor
simulation model Resistor
footprint 0603
footprint 0603M
footprint 0603L
footprint 0603_HV
footprint 0603S
pins: 1, 2

## ERJ-3RQFR22V
designator R?  ValueDisplayed: 0.22  (hidden comment: ERJ-3RQFR22V)
RES, 0.22, 1%, 0.1 W, 0603; Manufacturer: Panasonic; CompType: Resistor; Value: 0.22; Value_Code: R220; Tolerance_%: 1; Power_W: 0.1; Value2: 0.1W; TempCo: 300 ppm/C; SizeArea_mm2: 1.28; SizeX_mm: 1.6; SizeY_mm: 0.8; EIA_Code: E96; U/M: EA; AEC Category: Q200; Green_Lifecycle: Active; Green_REACh: Passed
signal-integrity model Resistor
simulation model Resistor
footprint 0603
footprint 0603M
footprint 0603L
footprint 0603_HV
footprint 0603S
pins: 1, 2

## ERJ-3RQFR27V
designator R?  ValueDisplayed: 0.27  (hidden comment: ERJ-3RQFR27V)
RES, 0.27, 1%, 0.1 W, 0603; Manufacturer: Panasonic; CompType: Resistor; Value: 0.27; Value_Code: R270; Tolerance_%: 1; Power_W: 0.1; Value2: 0.1W; TempCo: 300 ppm/C; SizeArea_mm2: 1.28; SizeX_mm: 1.6; SizeY_mm: 0.8; EIA_Code: E96; U/M: EA; AEC Category: Q200
signal-integrity model Resistor
simulation model Resistor
footprint 0603
footprint 0603M
footprint 0603L
footprint 0603_HV
footprint 0603S
pins: 1, 2

## ERJ-3RQFR33V
designator R?  ValueDisplayed: 0.33  (hidden comment: ERJ-3RQFR33V)
RES, 0.33, 1%, 0.1 W, 0603; Manufacturer: Panasonic; CompType: Resistor; Value: 0.33; Value_Code: R330; Tolerance_%: 1; Power_W: 0.1; Value2: 0.1W; TempCo: 300 ppm/C; SizeArea_mm2: 1.28; SizeX_mm: 1.6; SizeY_mm: 0.8; EIA_Code: E96; U/M: EA; AEC Category: Q200; Green_Lifecycle: Active; Green_REACh: Passed
signal-integrity model Resistor
simulation model Resistor
footprint 0603
footprint 0603M
footprint 0603L
footprint 0603_HV
footprint 0603S
pins: 1, 2

## ERJ-3RQFR39V
designator R?  ValueDisplayed: 0.39  (hidden comment: ERJ-3RQFR39V)
RES, 0.39, 1%, 0.1 W, 0603; Manufacturer: Panasonic; CompType: Resistor; Value: 0.39; Value_Code: R390; Tolerance_%: 1; Power_W: 0.1; Value2: 0.1W; TempCo: 300 ppm/C; SizeArea_mm2: 1.28; SizeX_mm: 1.6; SizeY_mm: 0.8; EIA_Code: E96; U/M: EA; AEC Category: Q200; Green_Lifecycle: Active; Green_REACh: Passed
signal-integrity model Resistor
simulation model Resistor
footprint 0603
footprint 0603M
footprint 0603L
footprint 0603_HV
footprint 0603S
pins: 1, 2

## ERJ-3RQFR47V
designator R?  ValueDisplayed: 0.47  (hidden comment: ERJ-3RQFR47V)
RES, 0.47, 1%, 0.1 W, 0603; Manufacturer: Panasonic; CompType: Resistor; Value: 0.47; Value_Code: R470; Tolerance_%: 1; Power_W: 0.1; Value2: 0.1W; TempCo: 300 ppm/C; SizeArea_mm2: 1.28; SizeX_mm: 1.6; SizeY_mm: 0.8; EIA_Code: E96; U/M: EA; AEC Category: Q200; Green_Lifecycle: Active; Green_REACh: Passed
signal-integrity model Resistor
simulation model Resistor
footprint 0603
footprint 0603M
footprint 0603L
footprint 0603_HV
footprint 0603S
pins: 1, 2

## ERJ-3RQFR51V
designator R?  ValueDisplayed: 0.51  (hidden comment: ERJ-3RQFR51V)
RES, 0.51, 1%, 0.1 W, AEC-Q200 Grade 1, 0603; Manufacturer: Panasonic; CompType: Resistor; Value: 0.51; Value_Code: R510; Tolerance_%: 1; Power_W: 0.1; Value2: 0.1W; TempCo: 300 ppm/C; SizeArea_mm2: 1.28; SizeX_mm: 1.6; SizeY_mm: 0.8; EIA_Code: E96; U/M: EA; AEC Category: Q200; AEC Qualified: Y; Green_Lifecycle: Active; Green_REACh: Passed
signal-integrity model Resistor
simulation model Resistor
footprint 0603
footprint 0603M
footprint 0603L
footprint 0603_HV
footprint 0603S
pins: 1, 2

## ERJ-3RQFR56V
designator R?  ValueDisplayed: 0.56  (hidden comment: ERJ-3RQFR56V)
RES, 0.56, 1%, 0.1 W, 0603; Manufacturer: Panasonic; CompType: Resistor; Value: 0.56; Value_Code: R560; Tolerance_%: 1; Power_W: 0.1; Value2: 0.1W; TempCo: 300 ppm/C; SizeArea_mm2: 1.28; SizeX_mm: 1.6; SizeY_mm: 0.8; EIA_Code: E96; U/M: EA; AEC Category: Q200; Green_Lifecycle: Active; Green_REACh: Passed
signal-integrity model Resistor
simulation model Resistor
footprint 0603
footprint 0603M
footprint 0603L
footprint 0603_HV
footprint 0603S
pins: 1, 2

## ERJ-3RQFR68V
designator R?  ValueDisplayed: 0.68  (hidden comment: ERJ-3RQFR68V)
RES, 0.68, 1%, 0.1 W, 0603; Manufacturer: Panasonic; CompType: Resistor; Value: 0.68; Value_Code: R680; Tolerance_%: 1; Power_W: 0.1; Value2: 0.1W; TempCo: 300 ppm/C; SizeArea_mm2: 1.28; SizeX_mm: 1.6; SizeY_mm: 0.8; EIA_Code: E96; U/M: EA; AEC Category: Q200
signal-integrity model Resistor
simulation model Resistor
footprint 0603
footprint 0603M
footprint 0603L
footprint 0603_HV
footprint 0603S
pins: 1, 2

## ERJ-3RQFR82V
designator R?  ValueDisplayed: 0.82  (hidden comment: ERJ-3RQFR82V)
RES, 0.82, 1%, 0.1 W, 0603; Manufacturer: Panasonic; CompType: Resistor; Value: 0.82; Value_Code: R820; Tolerance_%: 1; Power_W: 0.1; Value2: 0.1W; TempCo: 300 ppm/C; SizeArea_mm2: 1.28; SizeX_mm: 1.6; SizeY_mm: 0.8; EIA_Code: E96; U/M: EA; AEC Category: Q200
signal-integrity model Resistor
simulation model Resistor
footprint 0603
footprint 0603M
footprint 0603L
footprint 0603_HV
footprint 0603S
pins: 1, 2

## ERJ-3RSFR10V
designator R?  ValueDisplayed: 0.1  (hidden comment: ERJ-3RSFR10V)
RES, 0.1, 1%, 0.1 W, 0603; Manufacturer: Panasonic; CompType: Resistor; Value: 0.1; Value_Code: R100; Tolerance_%: 1; Value2: 0.1W; TempCo: 300 ppm/C; SizeArea_mm2: 1.28; SizeX_mm: 1.6; SizeY_mm: 0.8; EIA_Code: E96; U/M: EA; AEC Category: Q200; Green_Lifecycle: Not Set; Green_REACh: Incomplete
signal-integrity model Resistor
simulation model Resistor
footprint 0603
footprint 0603M
footprint 0603L
footprint 0603_HV
footprint 0603S
pins: 1, 2

## ERJ-3RSFR12V
designator R?  ValueDisplayed: 0.12  (hidden comment: ERJ-3RSFR12V)
RES, 0.12, 1%, 0.1 W, 0603; Manufacturer: Panasonic; CompType: Resistor; Value: 0.12; Value_Code: R120; Tolerance_%: 1; Power_W: 0.1; Value2: 0.1W; TempCo: 300 ppm/C; SizeArea_mm2: 1.28; SizeX_mm: 1.6; SizeY_mm: 0.8; EIA_Code: E96; U/M: EA; AEC Category: Q200
signal-integrity model Resistor
simulation model Resistor
footprint 0603
footprint 0603M
footprint 0603L
footprint 0603_HV
footprint 0603S
pins: 1, 2

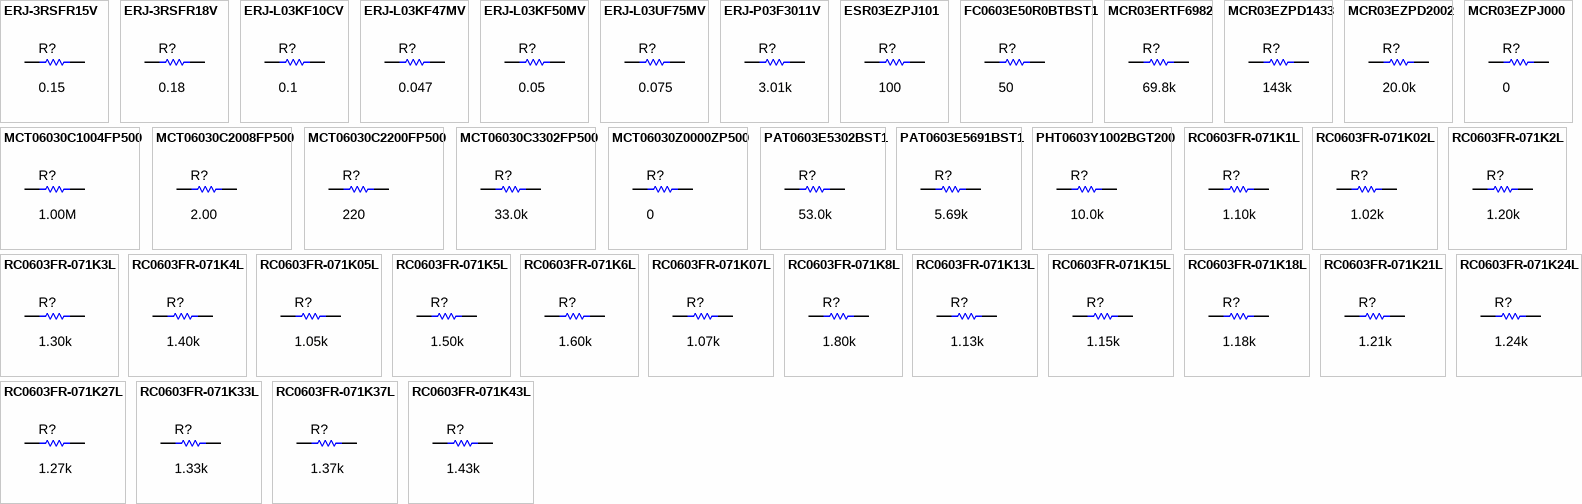
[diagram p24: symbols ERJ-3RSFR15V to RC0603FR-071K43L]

## ERJ-3RSFR15V
designator R?  ValueDisplayed: 0.15  (hidden comment: ERJ-3RSFR15V)
RES, 0.15, 1%, 0.1 W, 0603; Manufacturer: Panasonic; CompType: Resistor; Value: 0.15; Value_Code: R150; Tolerance_%: 1; Power_W: 0.1; Value2: 0.1W; TempCo: 300 ppm/C; SizeArea_mm2: 1.28; SizeX_mm: 1.6; SizeY_mm: 0.8; EIA_Code: E96; U/M: EA; AEC Category: Q200
signal-integrity model Resistor
simulation model Resistor
footprint 0603
footprint 0603M
footprint 0603L
footprint 0603_HV
footprint 0603S
pins: 1, 2

## ERJ-3RSFR18V
designator R?  ValueDisplayed: 0.18  (hidden comment: ERJ-3RSFR18V)
RES, 0.18, 1%, 0.1 W, 0603; Manufacturer: Panasonic; CompType: Resistor; Value: 0.18; Value_Code: R180; Tolerance_%: 1; Power_W: 0.1; Value2: 0.1W; TempCo: 300 ppm/C; SizeArea_mm2: 1.28; SizeX_mm: 1.6; SizeY_mm: 0.8; EIA_Code: E96; U/M: EA; AEC Category: Q200; Green_Lifecycle: Not Set; Green_REACh: Incomplete
signal-integrity model Resistor
simulation model Resistor
footprint 0603
footprint 0603M
footprint 0603L
footprint 0603_HV
footprint 0603S
pins: 1, 2

## ERJ-L03KF10CV
designator R?  ValueDisplayed: 0.1  (hidden comment: ERJ-L03KF10CV)
RES, 0.1, 1%, 0.1 W, 0603; Manufacturer: Panasonic; CompType: Resistor; Value: 0.1; Value_Code: R100; Tolerance_%: 1; Value2: 0.1W; TempCo: 200 ppm/C; SizeArea_mm2: 1.28; SizeX_mm: 1.6; SizeY_mm: 0.8; EIA_Code: E96; U/M: EA; AEC Category: Q200; Green_Lifecycle: Active; Green_REACh: Passed
signal-integrity model Resistor
simulation model Resistor
footprint 0603
footprint 0603M
footprint 0603L
footprint 0603_HV
footprint 0603S
pins: 1, 2

## ERJ-L03KF47MV
designator R?  ValueDisplayed: 0.047  (hidden comment: ERJ-L03KF47MV)
RES, 0.047, 1%, 0.1 W, 0603; Manufacturer: Panasonic; CompType: Resistor; Value: 0.047; Value_Code: R047; Tolerance_%: 1; Power_W: 0.1; Value2: 0.1W; TempCo: 200 ppm/C; SizeArea_mm2: 1.28; SizeX_mm: 1.6; SizeY_mm: 0.8; EIA_Code: E96; U/M: EA; AEC Category: Q200; Green_Lifecycle: Not Set; Green_REACh: Incomplete
signal-integrity model Resistor
simulation model Resistor
footprint 0603
footprint 0603M
footprint 0603L
footprint 0603_HV
footprint 0603S
pins: 1, 2

## ERJ-L03KF50MV
designator R?  ValueDisplayed: 0.05  (hidden comment: ERJ-L03KF50MV)
RES, 0.05, 1%, 0.1 W, 0603; Manufacturer: Panasonic; CompType: Resistor; Value: 0.05; Value_Code: R050; Tolerance_%: 1; Power_W: 0.1; Value2: 0.1W; TempCo: 200 ppm/C; SizeArea_mm2: 1.28; SizeX_mm: 1.6; SizeY_mm: 0.8; EIA_Code: E96; U/M: EA; AEC Category: Q200; Green_Lifecycle: Not Set; Green_REACh: Incomplete
signal-integrity model Resistor
simulation model Resistor
footprint 0603
footprint 0603M
footprint 0603L
footprint 0603_HV
footprint 0603S
pins: 1, 2

## ERJ-L03UF75MV
designator R?  ValueDisplayed: 0.075  (hidden comment: ERJ-L03UF75MV)
RES, 0.075, 1%, 0.1 W, 0603; Manufacturer: Panasonic; CompType: Resistor; Value: 0.075; Value_Code: R075; Tolerance_%: 1; Power_W: 0.1; Value2: 0.1W; TempCo: 200 ppm/C; SizeArea_mm2: 1.28; SizeX_mm: 1.6; SizeY_mm: 0.8; EIA_Code: E96; U/M: EA; AEC Category: Q200
signal-integrity model Resistor
simulation model Resistor
footprint 0603
footprint 0603M
footprint 0603L
footprint 0603_HV
footprint 0603S
pins: 1, 2

## ERJ-P03F3011V
designator R?  ValueDisplayed: 3.01k  (hidden comment: ERJ-P03F3011V)
RES, 3.01 k, 1%, 0.2 W, 0603; Manufacturer: Panasonic; CompType: Resistor; Value: 3.01k; Res_ohm: 3010; Value_Code: 3k01; Tolerance_%: 1; Power_W: 0.2; Value2: 0.2W; VDC_V: 150; TempCo: 200 ppm/C; SizeArea_mm2: 1.28; SizeX_mm: 1.6; SizeY_mm: 0.8; EIA_Code: E96; U/M: EA; AEC Category: Q200
signal-integrity model Resistor
simulation model Resistor
footprint 0603
footprint 0603M
footprint 0603L
footprint 0603_HV
footprint 0603S
pins: 1, 2

## ESR03EZPJ101
designator R?  ValueDisplayed: 100  (hidden comment: ESR03EZPJ101)
RES, 100, 5%, 0.25 W, AEC-Q200 Grade 0, 0603; Manufacturer: Rohm; CompType: Resistor; Value: 100; Value_Code: 100R; Tolerance_%: 5; Power_W: 0.25; Value2: 0.25W; VDC_V: 150; TempCo: 200 ppm/C; SizeArea_mm2: 1.28; SizeX_mm: 1.6; SizeY_mm: 0.8; SizeZ_mm: 1; EIA_Code: E24; U/M: EA; AEC Category: Q200; AEC Qualified: Y; AEC Grade: 0
signal-integrity model Resistor
simulation model Resistor
footprint 0603
footprint 0603M
footprint 0603L
footprint 0603_HV
footprint 0603S
pins: 1, 2

## FC0603E50R0BTBST1
designator R?  ValueDisplayed: 50  (hidden comment: FC0603E50R0BTBST1)
RES, 50, 0.1%, 0.125 W, 0603; Manufacturer: Vishay Thin Film; CompType: Resistor; Value: 50; Value_Code: 50R0; Tolerance_%: 0.1; Power_W: 0.125; Value2: 0.125W; TempCo: 25 ppm/C; SizeArea_mm2: 1.28; SizeX_mm: 1.6; SizeY_mm: 0.8; SizeZ_mm: 1; U/M: EA; AEC Category: Q200; AEC Qualified: N
signal-integrity model Resistor
simulation model Resistor
footprint 0603
footprint 0603M
footprint 0603L
footprint 0603_HV
footprint 0603S
pins: 1, 2

## MCR03ERTF6982
designator R?  ValueDisplayed: 69.8k  (hidden comment: MCR03ERTF6982)
RES, 69.8 k, 1%, 0.1 W, 0603; Manufacturer: Rohm; CompType: Resistor; Value: 69.8k; Res_ohm: 69800; Value_Code: 69k8; Tolerance_%: 1; Power_W: 0.1; Value2: 0.1W; VDC_V: 50; TempCo: 100 ppm/C; SizeArea_mm2: 1.28; SizeX_mm: 1.6; SizeY_mm: 0.8; EIA_Code: E96; U/M: EA; AEC Category: Q200; AEC Qualified: N
signal-integrity model Resistor
simulation model Resistor
footprint 0603
footprint 0603M
footprint 0603L
footprint 0603_HV
footprint 0603S
pins: 1, 2

## MCR03EZPD1433
designator R?  ValueDisplayed: 143k  (hidden comment: MCR03EZPD1433)
RES, 143 k, 0.5%, 0.1 W, 0603; Manufacturer: Rohm; CompType: Resistor; Value: 143k; Res_ohm: 143000; Tolerance_%: 0.5; Power_W: 0.1; Value2: 0.1W; VDC_V: 50; TempCo: 50 ppm/C; SizeArea_mm2: 1.28; SizeX_mm: 1.6; SizeY_mm: 0.8; SizeZ_mm: 1; EIA_Code: E192; U/M: EA; AEC Category: Q200; AEC Qualified: N
signal-integrity model Resistor
simulation model Resistor
footprint 0603
footprint 0603M
footprint 0603L
footprint 0603_HV
footprint 0603S
pins: 1, 2

## MCR03EZPD2002
designator R?  ValueDisplayed: 20.0k  (hidden comment: MCR03EZPD2002)
RES, 20.0 k, 0.5%, 0.1 W, 0603; Manufacturer: Rohm; CompType: Resistor; Value: 20.0k; Res_ohm: 20000; Value_Code: 20k0; Tolerance_%: 0.5; Power_W: 0.1; Value2: 0.1W; VDC_V: 50; TempCo: 50 ppm/C; SizeArea_mm2: 1.28; SizeX_mm: 1.6; SizeY_mm: 0.8; SizeZ_mm: 1; EIA_Code: E192; U/M: EA; AEC Category: Q200; AEC Qualified: N
signal-integrity model Resistor
simulation model Resistor
footprint 0603
footprint 0603M
footprint 0603L
footprint 0603_HV
footprint 0603S
pins: 1, 2

## MCR03EZPJ000
designator R?  ValueDisplayed: 0  (hidden comment: MCR03EZPJ000)
RES, 0, 5%, 0.1 W, 0603; Manufacturer: Rohm; CompType: Resistor; Value: 0; Value_Code: 0000; Tolerance_%: 5; Power_W: 0.1; Value2: 0.1W; VDC_V: 50; TempCo: 400 ppm/C; SizeArea_mm2: 1.28; SizeX_mm: 1.6; SizeY_mm: 0.8; SizeZ_mm: 1; EIA_Code: E24; U/M: EA; AEC Category: Q200; AEC Qualified: N; Green_Lifecycle: Active; Green_REACh: Passed
signal-integrity model Resistor
simulation model Resistor
footprint 0603
footprint 0603M
footprint 0603L
footprint 0603_HV
footprint 0603S
pins: 1, 2

## MCT06030C1004FP500
designator R?  ValueDisplayed: 1.00M  (hidden comment: MCT06030C1004FP500)
RES, 1.00 M, 1%, 0.125 W, 0603; Manufacturer: Vishay/Beyschlag; CompType: Resistor; Value: 1.00Meg; Res_ohm: 1000000; Value_Code: 1M00; Tolerance_%: 1; Power_W: 0.125; Value2: 0.125W; VDC_V: 75; TempCo: 50 ppm/C; SizeArea_mm2: 1.28; SizeX_mm: 1.6; SizeY_mm: 0.8; EIA_Code: E96; U/M: EA; AEC Category: Q200; AEC Qualified: N; Green_Lifecycle: Active; Green_REACh: Passed
signal-integrity model Resistor
simulation model Resistor
footprint 0603
footprint 0603M
footprint 0603L
footprint 0603_HV
footprint 0603S
pins: 1, 2

## MCT06030C2008FP500
designator R?  ValueDisplayed: 2.00  (hidden comment: MCT06030C2008FP500)
RES, 2.00, 1%, 0.125 W, 0603; Manufacturer: Vishay/Beyschlag; CompType: Resistor; Value: 2.00; Res_ohm: 2; Value_Code: 2R00; Tolerance_%: 1; Power_W: 0.125; Value2: 0.125W; TempCo: 50 ppm/C; SizeArea_mm2: 1.28; SizeX_mm: 1.6; SizeY_mm: 0.8; EIA_Code: E96; U/M: EA; AEC Category: Q200; AEC Qualified: N
signal-integrity model Resistor
simulation model Resistor
footprint 0603
footprint 0603M
footprint 0603L
footprint 0603_HV
footprint 0603S
pins: 1, 2

## MCT06030C2200FP500
designator R?  ValueDisplayed: 220  (hidden comment: MCT06030C2200FP500)
RES, 220, 1%, 0.125 W, 0603; Manufacturer: Vishay/Beyschlag; CompType: Resistor; Value: 220; Value_Code: 220R; Tolerance_%: 1; Power_W: 0.125; Value2: 0.125W; VDC_V: 75; TempCo: 50 ppm/C; SizeArea_mm2: 1.28; SizeX_mm: 1.6; SizeY_mm: 0.8; U/M: EA; AEC Category: Q200; AEC Qualified: N
signal-integrity model Resistor
simulation model Resistor
footprint 0603
footprint 0603M
footprint 0603L
footprint 0603_HV
footprint 0603S
pins: 1, 2

## MCT06030C3302FP500
designator R?  ValueDisplayed: 33.0k  (hidden comment: MCT06030C3302FP500)
RES, 33.0 k, 1%, 0.125 W, 0603; Manufacturer: Vishay/Beyschlag; CompType: Resistor; Value: 33.0k; Res_ohm: 33000; Value_Code: 33k0; Tolerance_%: 1; Power_W: 0.125; Value2: 0.125W; VDC_V: 75; TempCo: 50 ppm/C; SizeArea_mm2: 1.28; SizeX_mm: 1.6; SizeY_mm: 0.8; U/M: EA; AEC Category: Q200; AEC Qualified: N
signal-integrity model Resistor
simulation model Resistor
footprint 0603
footprint 0603M
footprint 0603L
footprint 0603_HV
footprint 0603S
pins: 1, 2

## MCT06030Z0000ZP500
designator R?  ValueDisplayed: 0  (hidden comment: MCT06030Z0000ZP500)
RES, 0, 5%, 0.125 W, 0603; Manufacturer: Vishay/Beyschlag; CompType: Resistor; Value: 0; Value_Code: 0000; Tolerance_%: 5; Power_W: 0.125; Value2: 0.125W; TempCo: ppm/C; SizeArea_mm2: 1.28; SizeX_mm: 1.6; SizeY_mm: 0.8; SizeZ_mm: 1; EIA_Code: E24; U/M: EA; AEC Category: Q200; AEC Qualified: N; Green_Lifecycle: Active; Green_REACh: Passed
signal-integrity model Resistor
simulation model Resistor
footprint 0603
footprint 0603M
footprint 0603L
footprint 0603_HV
footprint 0603S
pins: 1, 2

## PAT0603E5302BST1
designator R?  ValueDisplayed: 53.0k  (hidden comment: PAT0603E5302BST1)
RES, 53.0 k, 0.1%, 0.15 W, AEC-Q200 Grade 0, 0603; Manufacturer: Vishay-Dale; CompType: Resistor; Value: 53.0k; Res_ohm: 53000; Value_Code: 53k0; Tolerance_%: 0.1; Power_W: 0.15; Value2: 0.15W; VDC_V: 75; TempCo: 25 ppm/C; SizeArea_mm2: 1.28; SizeX_mm: 1.6; SizeY_mm: 0.8; SizeZ_mm: 1; EIA_Code: E192; U/M: EA; AEC Category: Q200; AEC Qualified: Y; AEC Grade: 0
signal-integrity model Resistor
simulation model Resistor
footprint 0603
footprint 0603M
footprint 0603L
footprint 0603_HV
footprint 0603S
pins: 1, 2

## PAT0603E5691BST1
designator R?  ValueDisplayed: 5.69k  (hidden comment: PAT0603E5691BST1)
RES, 5.69 k, 0.1%, 0.15 W, 0603; Manufacturer: Vishay-Dale; CompType: Resistor; Value: 5.69k; Res_ohm: 5690; Value_Code: 5k69; Tolerance_%: 0.1; Power_W: 0.15; Value2: 0.15W; VDC_V: 75; TempCo: 25 ppm/C; SizeArea_mm2: 1.28; SizeX_mm: 1.6; SizeY_mm: 0.8; SizeZ_mm: 1; EIA_Code: E192; U/M: EA; AEC Category: Q200
signal-integrity model Resistor
simulation model Resistor
footprint 0603
footprint 0603M
footprint 0603L
footprint 0603_HV
footprint 0603S
pins: 1, 2

## PHT0603Y1002BGT200
designator R?  ValueDisplayed: 10.0k  (hidden comment: PHT0603Y1002BGT200)
RES, 10.0 k, 0.1%, 0.0375 W, 0603; Manufacturer: Vishay Sfernice; CompType: Resistor; Value: 10.0k; Res_ohm: 10000; Value_Code: 10k0; Tolerance_%: 0.1; Power_W: 0.0375; VDC_V: 75; TempCo: 15 ppm/C; SizeArea_mm2: 1.28; SizeX_mm: 1.6; SizeY_mm: 0.8; SizeZ_mm: 1; EIA_Code: E192; U/M: EA; AEC Category: Q200
signal-integrity model Resistor
simulation model Resistor
footprint 0603
footprint 0603M
footprint 0603L
footprint 0603_HV
footprint 0603S
pins: 1, 2

## RC0603FR-071K1L
designator R?  ValueDisplayed: 1.10k  (hidden comment: RC0603FR-071K1L)
RES, 1.10 k, 1%, 0.1 W, 0603; Manufacturer: Yageo America; CompType: Resistor; Value: 1.10k; Res_ohm: 1100; Value_Code: 1k10; Tolerance_%: 1; Power_W: 0.1; Value2: 0.1W; VDC_V: 150; TempCo: 200 ppm/C; SizeArea_mm2: 1.28; SizeX_mm: 1.6; SizeY_mm: 0.8; EIA_Code: E96; U/M: EA; AEC Category: Q200; Green_Lifecycle: Active; Green_REACh: Passed
signal-integrity model Resistor
simulation model Resistor
footprint 0603
footprint 0603M
footprint 0603L
footprint 0603_HV
footprint 0603S
pins: 1, 2

## RC0603FR-071K02L
designator R?  ValueDisplayed: 1.02k  (hidden comment: RC0603FR-071K02L)
RES, 1.02 k, 1%, 0.1 W, 0603; Manufacturer: Yageo America; CompType: Resistor; Value: 1.02k; Res_ohm: 1020; Value_Code: 1k02; Tolerance_%: 1; Power_W: 0.1; Value2: 0.1W; VDC_V: 150; TempCo: 200 ppm/C; SizeArea_mm2: 1.28; SizeX_mm: 1.6; SizeY_mm: 0.8; EIA_Code: E96; U/M: EA; AEC Category: Q200
signal-integrity model Resistor
simulation model Resistor
footprint 0603
footprint 0603M
footprint 0603L
footprint 0603_HV
footprint 0603S
pins: 1, 2

## RC0603FR-071K2L
designator R?  ValueDisplayed: 1.20k  (hidden comment: RC0603FR-071K2L)
RES, 1.20 k, 1%, 0.1 W, 0603; Manufacturer: Yageo America; CompType: Resistor; Value: 1.20k; Res_ohm: 1200; Value_Code: 1k20; Tolerance_%: 1; Power_W: 0.1; Value2: 0.1W; VDC_V: 150; TempCo: 200 ppm/C; SizeArea_mm2: 1.28; SizeX_mm: 1.6; SizeY_mm: 0.8; U/M: EA; AEC Category: Q200; Green_Lifecycle: Active; Green_REACh: Passed
signal-integrity model Resistor
simulation model Resistor
footprint 0603
footprint 0603M
footprint 0603L
footprint 0603_HV
footprint 0603S
pins: 1, 2

## RC0603FR-071K3L
designator R?  ValueDisplayed: 1.30k  (hidden comment: RC0603FR-071K3L)
RES, 1.30 k, 1%, 0.1 W, 0603; Manufacturer: Yageo America; CompType: Resistor; Value: 1.30k; Res_ohm: 1300; Value_Code: 1k30; Tolerance_%: 1; Power_W: 0.1; Value2: 0.1W; VDC_V: 150; TempCo: 200 ppm/C; SizeArea_mm2: 1.28; SizeX_mm: 1.6; SizeY_mm: 0.8; EIA_Code: E96; U/M: EA; AEC Category: Q200
signal-integrity model Resistor
simulation model Resistor
footprint 0603
footprint 0603M
footprint 0603L
footprint 0603_HV
footprint 0603S
pins: 1, 2

## RC0603FR-071K4L
designator R?  ValueDisplayed: 1.40k  (hidden comment: RC0603FR-071K4L)
RES, 1.40 k, 1%, 0.1 W, 0603; Manufacturer: Yageo America; CompType: Resistor; Value: 1.40k; Res_ohm: 1400; Value_Code: 1k40; Tolerance_%: 1; Power_W: 0.1; Value2: 0.1W; VDC_V: 150; TempCo: 200 ppm/C; SizeArea_mm2: 1.28; SizeX_mm: 1.6; SizeY_mm: 0.8; EIA_Code: E96; U/M: EA; AEC Category: Q200; Green_Lifecycle: Active; Green_REACh: Passed
signal-integrity model Resistor
simulation model Resistor
footprint 0603
footprint 0603M
footprint 0603L
footprint 0603_HV
footprint 0603S
pins: 1, 2

## RC0603FR-071K05L
designator R?  ValueDisplayed: 1.05k  (hidden comment: RC0603FR-071K05L)
RES, 1.05 k, 1%, 0.1 W, 0603; Manufacturer: Yageo America; CompType: Resistor; Value: 1.05k; Res_ohm: 1050; Value_Code: 1k05; Tolerance_%: 1; Power_W: 0.1; Value2: 0.1W; VDC_V: 150; TempCo: 200 ppm/C; SizeArea_mm2: 1.28; SizeX_mm: 1.6; SizeY_mm: 0.8; EIA_Code: E96; U/M: EA; AEC Category: Q200
signal-integrity model Resistor
simulation model Resistor
footprint 0603
footprint 0603M
footprint 0603L
footprint 0603_HV
footprint 0603S
pins: 1, 2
